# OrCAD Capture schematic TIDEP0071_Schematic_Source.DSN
size C; title: TIDEP0071; rev: A7E; company: Texas Instruments, Inc.
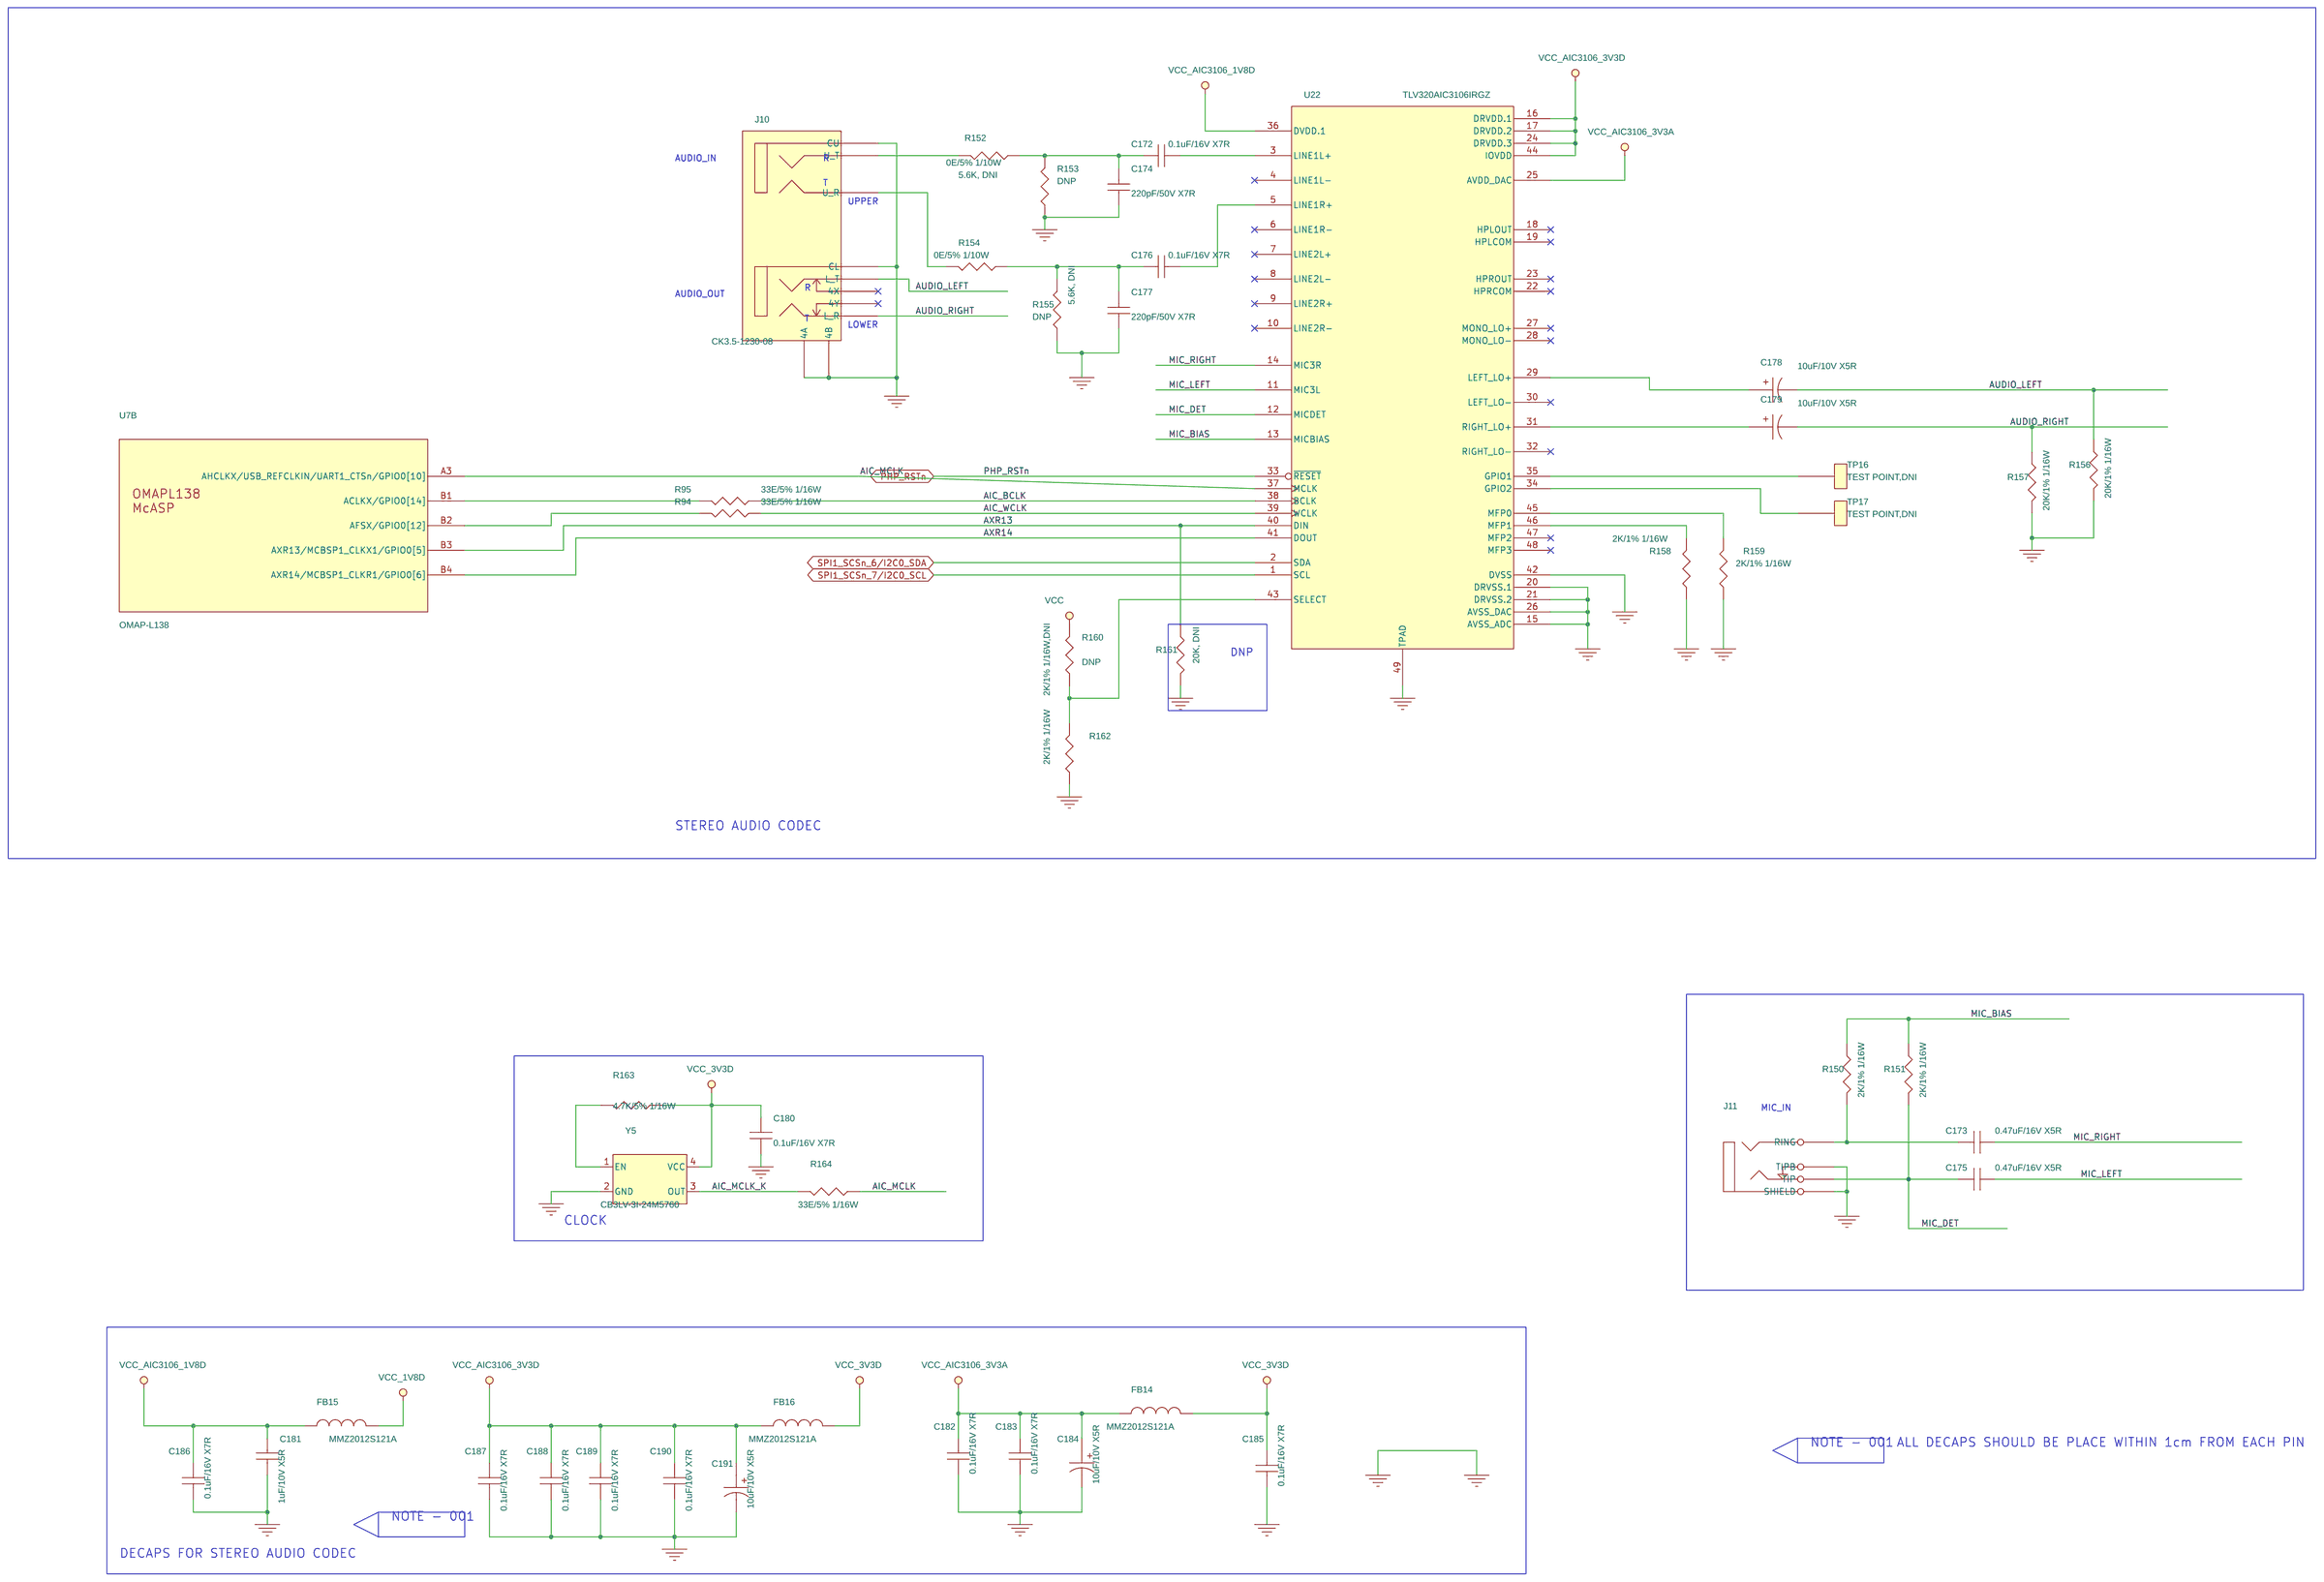
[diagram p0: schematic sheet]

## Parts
C172  0.1uF/16V X7R  [0402]
C173  0.47uF/16V X5R  [0402]
C174  220pF/50V X7R  [0402]
C175  0.47uF/16V X5R  [0402]
C176  0.1uF/16V X7R  [0402]
C177  220pF/50V X7R  [0402]
C178  10uF/10V X5R  [0805]
C179  10uF/10V X5R  [0805]
C180  0.1uF/16V X7R  [0402]
C181  1uF/10V X5R  [0402]
C182  0.1uF/16V X7R  [0402]
C183  0.1uF/16V X7R  [0402]
C184  10uF/10V X5R  [0805]
C185  0.1uF/16V X7R  [0402]
C186  0.1uF/16V X7R  [0402]
C187  0.1uF/16V X7R  [0402]
C188  0.1uF/16V X7R  [0402]
C189  0.1uF/16V X7R  [0402]
C190  0.1uF/16V X7R  [0402]
C191  10uF/10V X5R  [0805]
FB14  MMZ2012S121A  [0805]
FB15  MMZ2012S121A  [0805]
FB16  MMZ2012S121A  [0805]
J10  CK3.5-1230-08  [CX3_5-1230-08]
J11  STX-3500-4NTR  [STX3500]
R94  33E/5% 1/16W  [0402]
R95  33E/5% 1/16W  [0402]
R150  2K/1% 1/16W  [0402]
R151  2K/1% 1/16W  [0402]
R152  0E/5% 1/10W  [0402]
R153  5.6K, DNI  [0402]
R154  0E/5% 1/10W  [0402]
R155  5.6K, DNI  [0402]
R156  20K/1% 1/16W  [0402]
R157  20K/1% 1/16W  [0402]
R158  2K/1% 1/16W  [0402]
R159  2K/1% 1/16W  [0402]
R160  2K/1% 1/16W,DNI  [0402]
R161  20K, DNI  [0402]
R162  2K/1% 1/16W  [0402]
R163  4.7K/5% 1/16W  [0402]
R164  33E/5% 1/16W  [0402]
TP16  TEST POINT,DNI  [tp]
TP17  TEST POINT,DNI  [tp]
U7  OMAP-L138  [bga361_w19_p8_16x16]  (section B)
U22  TLV320AIC3106IRGZ  [QFN48_25V]
Y5  CB3LV-3I-24M5760  [OSC4_90-100SMD_130X200]

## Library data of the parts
C172 C176 C182 C183 C185-C190 = CAPACITOR_NON-POL: CAP .10UF 16V CERAMIC X7R; MAKE: Kemet; Manufacturer: Murata; Manufacturers part Reference: GRM155R71C104KA88D; Package: 0603; ROHS STATUS: COMPLIANT; SOURCE: DIGIKEY; TEMP Grade: -55 to +125; TEMPERATURE GRADE: -55 to +125
C173 C175 = CAPACITOR_NON-POL: CAP CER .47UF 16V X5R 0402; MAKE: Kemet; Manufacturer: TDK; Manufacturers part Reference: C1005X5R1C474M050BC; Package: 0603; ROHS STATUS: COMPLIANT; TEMP Grade: -55 to +125; TEMPERATURE GRADE: -55 to +125
C174 C177 = CAPACITOR_NON-POL: CAP 220PF 50V CERAMIC X7R 0402; MAKE: Kemet; Manufacturer: Yageo; Manufacturers part Reference: CC0402KRX7R9BB221; Package: 0603; ROHS STATUS: COMPLIANT; TEMP Grade: -55 to +125; TEMPERATURE GRADE: -55 to +125
C178 C179 C184 C191 = CAP_POL: CAP 10UF 10V CERAMIC X5R 0805; MAKE: Panasonic; MANUFACTURER: TDK; Manufacturers part Reference: C2012X5R1A106M125AB; Package: 1206; RoHS Status: COMPLIANT; TEMPERATURE GRADE: -55 to +125
C180 = CAP_NP_1: CAP .10UF 16V CERAMIC X7R; MAKE: Kemet; Manufacturer: Murata; Manufacturers part Reference: GRM155R71C104KA88D; Package: 0603; Part #: 101587-1100R; ROHS STATUS: COMPLIANT; TEMP Grade: -55 to +125; TEMPERATURE GRADE: -55 to +125
C181 = CAPACITOR_NON-POL: CAP CER 1UF 10V X5R 0402; MAKE: Kemet; Manufacturer: Murata; Manufacturers part Reference: GRM155R61A105KE15D; Package: 0603; ROHS STATUS: COMPLIANT; TEMP Grade: -55 to +125; TEMPERATURE GRADE: -55 to +125
FB14-FB16 = INDUCTOR: FERRITE CHIP 120 OHM 800MA 0805; MAKE: TDK; MANUFACTURER: TDK; ROHS STATUS: COMPLIANT; TEMP Grade: -55 to +125; TEMPERATURE GRADE: -55 to +125
J10 = CX3_0.5-1230-08: CONN STEREO JACK 3.5MM 3/3P PCB; Manufacturer: Fosen Electronics Technology Co. Ltd. / Zai Kuai Sales, Ltd. Co.
J11 = Kycon_ST-3500_3: Phone Connectors 3.5mm SMT STEREO JAK 4P NON THREADED T/R; Manufacturer: Kycon; ROHS STATUS: COMPLIANT
R94 R95 R164 = RESISTOR: RES 33 OHM 1/16W 5% 0402 SMD; ID: 6936; MAKE: Panasonic; MANUFACTURER: Yageo; MFR PART NO.: ERJ-3GEYJ330V; Manufacturers part Reference: RC0402FR-0733RL; Package: 603; RoHS Status: COMPLIANT; SOURCE: DIGIKEY; TEMPERATURE GRADE: -55 to +155
R150 R151 = R: RES 2K OHM 1/16W 1% 0402 SMD; MANUFACTURER: Vishay Dale; Manufacturers part Reference: CRCW04022K00FKED; Package: 0603; ROHS STATUS: COMPLIANT; TEMPERATURE GRADE: -55 to +155
R152 R154 = R: RES ZERO OHM 1/10W 5% 0402; ID: 5801; MAKE: Panasonic; Manufacturer: Panasonic; Manufacturers part Reference: ERJ-2GE0R00X; Package: 603; RoHS Status: COMPLIANT; SOURCE: DIGIKEY; TEMPERATURE GRADE: -55 to +125
R153 R155 = R: RES 5.60K OHM 1/16W 1% 0402; BOM notes: DNP; ID: 5801; INSTALLED: DNI; MAKE: Panasonic; Manufacturer: Yageo; Manufacturers part Reference: AC0402FR-075K6L; Package: 603; RoHS Status: COMPLIANT; SOURCE: DIGIKEY; TEMPERATURE GRADE: -55 to +125
R156 R157 = R: RES 20K OHM 1/16W 1% 0402 SMD; MANUFACTURER: Yageo; Manufacturers part Reference: RC0402FR-0720KL; Package: 0603; ROHS STATUS: COMPLIANT; TEMPERATURE GRADE: -55 to +155
R158 R159 R162 = R: RES 2K OHM 1/16W 1% 0402 SMD; ID: 68112; MAKE: Panasonic; MANUFACTURER: Vishay Dale; Manufacturers part Reference: CRCW04022K00FKED; Package: 0603; RoHS Status: COMPLIANT; TEMPERATURE GRADE: -55 to +155
R160 = R: RES 2K OHM 1/16W 1% 0402 SMD; BOM NOTES: DNP; ID: 68112; INSTALLED: DNI; MAKE: Panasonic; MANUFACTURER: Vishay Dale; Manufacturers part Reference: CRCW04022K00FKED; Package: 0603; RoHS Status: COMPLIANT; TEMPERATURE GRADE: -55 to +155
R161 = R: RES 20K OHM 1/16W 1% 0402 SMD; BOM NOTES: DNP; INSTALLED: DNI; MANUFACTURER: Yageo; Manufacturers part Reference: RC0402FR-0720KL; Package: 0603; ROHS STATUS: COMPLIANT; TEMPERATURE GRADE: -55 to +155
R163 = R: RES 4.7K OHM 1/16W 5% 0402 SMD; ID: 5801; MAKE: Panasonic; Manufacturer: Yageo; Manufacturers part Reference: RC0402JR-074K7L; Package: 603; RoHS Status: COMPLIANT; SOURCE: DIGIKEY; TEMPERATURE GRADE: -55 to +125
TP16 TP17 = TEST_POINT: CONN HEADER 1POS .100" SGL GOLD; INSTALLED: DNI; MAKE: Samtec; MANUFACTURER: SAMTEC; Manufacturers part Reference: TSW-101-07-G-S; Package: THROUGH HOLE; ROHS STATUS: COMPLIANT; SOURCE: DIGIKEY; TEMPERATURE GRADE: -55 to +125
U7 = OMAP-L138
U22 = TLV320AIC3106_5: LOW POWER STERO AUDIO CODEC; MANUFACTURER: TI; Package: 80-VFBGA; Part #: 102800-0001R; ROHS STATUS: COMPLIANT; TEMPERATURE GRADE: –40°C to 85°C
Y5 = OSC4_SM_0: OSCILLATOR 24.5760 MHZ 3.3V SMD; MANUFACTURER: ABRACON; Manufacturers part Reference: ASFL1-24.576MHZ-EC-T; Package: SMD; Part #: 102201-2457R; ROHS STATUS: COMPLIANT; SD PCB Footprint: CB3LV; TEMPERATURE GRADE: -40°C ~ 85°C

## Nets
GND: C174.1 C177.1 C180.2 C181.2 C182.2 C183.2 C184.2 C185.2 C186.2 C187.2 C188.2 C189.2 C190.2 C191.2 J10.1(CL) J10.2(CU) J10.9(4A) J10.10(4B) J11.1(SHIELD) J11.4(TIPB) R153.1 R155.1 R156.2 R157.2 R158.1 R159.1 R161.2 R162.1 U22.15(AVSS_ADC) U22.20(DRVSS.1) U22.21(DRVSS.2) U22.26(AVSS_DAC) U22.42(DVSS) U22.49(TPAD) Y5.2(GND)
VCC_1V8D: FB15.2
VCC_3V3D: C180.1 C185.1 FB14.2 FB16.2 R160.2 R163.1 Y5.4(VCC)
VCC_AIC3106_1V8D: C181.1 C186.1 FB15.1 U22.36(DVDD.1)
VCC_AIC3106_3V3A: C182.1 C183.1 C184.1 FB14.1 U22.25(AVDD_DAC)
VCC_AIC3106_3V3D: C187.1 C188.1 C189.1 C190.1 C191.1 FB16.1 U22.16(DRVDD.1) U22.17(DRVDD.2) U22.24(DRVDD.3) U22.44(IOVDD)
AIC_BCLK: R95.1 U22.38(BCLK)
AIC_MCLK: R164.1 U7.A3(AHCLKX/USB_REFCLKIN/UART1_CTSn/GPIO0[10]) U22.37(MCLK)
AIC_MCLK_K: R164.2 Y5.3(OUT)
AIC_WCLK: R94.1 U22.39(WCLK)
AUDIO_LEFT: C178.2 J10.3(L_T) R156.1
AUDIO_RIGHT: C179.2 J10.4(L_R) R157.1
AXR13: R161.1 U7.B3(AXR13/MCBSP1_CLKX1/GPIO0[5]) U22.40(DIN)
AXR14: U7.B4(AXR14/MCBSP1_CLKR1/GPIO0[6]) U22.41(DOUT)
MIC_BIAS: R150.1 R151.1 U22.13(MICBIAS)
MIC_DET: C175.2 J11.2(TIP) R151.2 U22.12(MICDET)
MIC_LEFT: C175.1 U22.11(MIC3L)
MIC_RIGHT: C173.1 U22.14(MIC3R)
PHP_RSTn: U22.33(~{RESET})
SPI1_SCSn_6/I2C0_SDA: U22.2(SDA)
SPI1_SCSn_7/I2C0_SCL: U22.1(SCL)
N17141238: R163.2 Y5.1(EN)
N17232839: TP16.1 U22.35(GPIO1)
N17232859: TP17.1 U22.34(GPIO2)
N17232911: C179.1 U22.31(RIGHT_LO+)
N17232927: C178.1 U22.29(LEFT_LO+)
N17232971: R158.2 U22.46(MFP1)
N17232975: R159.2 U22.45(MFP0)
N17235121: R160.1 R162.2 U22.43(SELECT)
N17236450: C176.1 C177.2 R154.1 R155.2
N17236452: C172.1 C174.2 R152.1 R153.2
N17236454: C172.2 U22.3(LINE1L+)
N17236480: C176.2 U22.5(LINE1R+)
N17236492: J10.7(U_R) R154.2
N17236496: J10.8(U_T) R152.2
N27473148: C173.2 J11.3(RING) R150.2
N29148842: R94.2 U7.B2(AFSX/GPIO0[12])
N29149440: R95.2 U7.B1(ACLKX/GPIO0[14])

Not connected (* = marked no-connect by the designer): J10 5(4X)* 6(4Y)*; U22 4(LINE1L-)* 6(LINE1R-)* 7(LINE2L+)* 8(LINE2L-)* 9(LINE2R+)* 10(LINE2R-)* 18(HPLOUT)* 19(HPLCOM)* 22(HPRCOM)* 23(HPROUT)* 27(MONO_LO+)* 28(MONO_LO-)* 30(LEFT_LO-)* 32(RIGHT_LO-)* 47(MFP2)* 48(MFP3)*

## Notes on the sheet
- AUDIO_IN
- R
- T
- UPPER
- AUDIO_OUT
- R
- T
- LOWER
- DNP
- STEREO AUDIO CODEC
- MIC_IN
- CLOCK
- NOTE - 001
- ALL DECAPS SHOULD BE PLACE WITHIN 1cm FROM EACH PIN
- NOTE - 001
- DECAPS FOR STEREO AUDIO CODEC
